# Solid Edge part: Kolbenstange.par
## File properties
Username: ahadarics
Dokumentum tartalom típus: 0
Author: ahadarics
Last saved by: ahadarics
Revision: 79
Sűrűség: 0,000 kg/m^3
Pontosság: 0,990
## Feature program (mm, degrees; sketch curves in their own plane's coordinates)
base feature "unnamed BaseFeature 1"
thread "unnamed Thread 1"
sketch for "unnamed Protrusion 1" plane through (81, 0, 0) normal (1, 0, 0) x-axis (0, 0, 1)
  circle centre (0, 0) radius 40
extrude "unnamed Protrusion 1" add finite 24 along -normal
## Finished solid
Body 1: solid body, 17 faces, 23 edges, 8 vertices.
  Faces by surface: plane 8, cylinder 4, torus 3, cone 2
  Edges by curve: circle 13, line 6, ellipse 2, intersection 2
Bounding box of the edges (mm; curved faces can reach further): 96.000 x 80.000 x 80.000, from (-15, -40, -40) to (81, 40, 40).
Cylindrical faces by radius (mm): R6.75 x1, R8 x1, R10 x1, R40 x1
Conical faces (half-angle, radius in mm at the cone's reference point): 20 deg R7.4 x1, 60 deg R7.475 x1
Toroidal faces (ring radius, tube radius in mm): R7.15 r0.4 x2, R8.2 r1.8 x1
Planar faces by outward normal: +x 1, +y 1, -x 3, -y 1, oblique 2
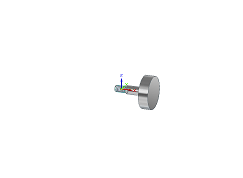
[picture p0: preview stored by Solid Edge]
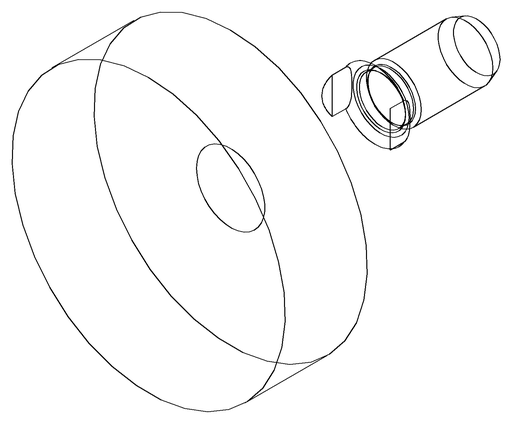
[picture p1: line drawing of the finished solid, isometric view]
